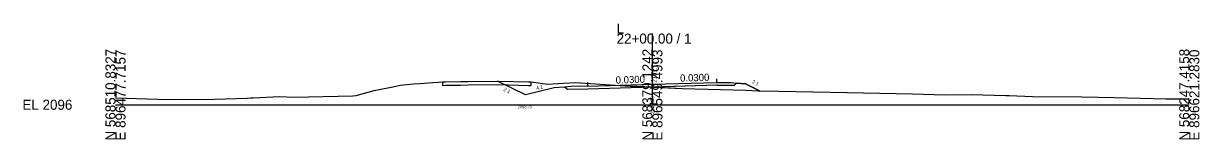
# Model space of a CAD drawing. Extents: x -26 to 1603, y -10 to 13527.
# Drawn here: x -25.7 to 302.8, y 9490.3 to 9522.7 of the extents above; entities that cross this region are included whole.
import ezdxf

# ---------------------------------------------------------------- set-up
doc = ezdxf.new("R2010")
doc.units = 0
for name, color, linetype in [('Default', 7, 'Continuous'), ('Exist XS Center Line Elevation Label', 7, 'Continuous'), ('Exist XS Ground Line', 7, 'Continuous'), ('Old_Level_61', 7, 'Continuous'), ('Old_Level_63', 7, 'Continuous'), ('Prop XS Ditch Slope Text', 7, 'Continuous'), ('Prop XS Ditch Standard Text', 7, 'Continuous'), ('Prop XS Earthwork Shape', 7, 'Continuous'), ('Prop XS EOT Tick Mark', 7, 'Continuous'), ('Prop XS Finish Grade', 7, 'Continuous'), ('Prop XS Finish Grade Earthwork', 7, 'Continuous'), ('Prop XS Finish Grade Paved Shoulder', 7, 'Continuous'), ('Prop XS Finish Grade Pavement', 7, 'Continuous'), ('Prop XS Side Slope Text', 7, 'Continuous'), ('Prop XS Subgrade Earthwork', 7, 'Continuous'), ('Prop XSC Text', 7, 'Continuous')]:
    doc.layers.add(name, color=color, linetype=linetype)

msp = doc.modelspace()

# ---------------------------------------------------------------- linework, layer by layer
at = {"layer": 'Exist XS Ground Line'}
for p, q in [((73.7, 9504.24), (77.47, 9505)), ((77.47, 9505), (79.57, 9505.46)), ((79.57, 9505.46), (83.26, 9505.8)), ((83.26, 9505.8), (85.12, 9505.92)), ((85.12, 9505.92), (88.7, 9506.17)), ((88.7, 9506.17), (90.23, 9506.28)), ((90.23, 9506.28), (91.4, 9506.41)), ((91.4, 9506.41), (92.17, 9506.44)), ((92.17, 9506.44), (96.35, 9506.49)), ((96.35, 9506.49), (98.55, 9506.52)), ((98.55, 9506.52), (107.03, 9506.62)), ((107.03, 9506.62), (115.41, 9506.39)), ((115.41, 9506.39), (116.12, 9506.37)), ((116.12, 9506.37), (116.74, 9506.27)), ((116.74, 9506.27), (120.68, 9505.73)), ((120.68, 9505.73), (123.55, 9505.9)), ((123.55, 9505.9), (128.49, 9506.25)), ((128.49, 9506.25), (142.4, 9505.31)), ((142.4, 9505.31), (143.8, 9505.21)), ((143.8, 9505.21), (145.77, 9505.15)), ((145.77, 9505.15), (150, 9504.96)), ((150, 9504.96), (158.32, 9504.57)), ((158.32, 9504.57), (165.45, 9504.39)), ((0, 9501.95), (11.83, 9501.6)), ((11.83, 9501.6), (18.94, 9501.44)), ((18.94, 9501.44), (21.67, 9501.53)), ((21.67, 9501.53), (24.64, 9501.5)), ((24.64, 9501.5), (36.8, 9501.87)), ((36.8, 9501.87), (37.74, 9501.92)), ((37.74, 9501.92), (38.45, 9501.94)), ((38.45, 9501.94), (45.83, 9502.34)), ((45.83, 9502.34), (49.83, 9502.16)), ((49.83, 9502.16), (66.28, 9502.5)), ((66.28, 9502.5), (67.26, 9502.6)), ((67.26, 9502.6), (72.3, 9503.95)), ((72.3, 9503.95), (73.7, 9504.24)), ((165.45, 9504.39), (176.1, 9504.04)), ((176.1, 9504.04), (179.59, 9503.91)), ((179.59, 9503.91), (185.22, 9503.8)), ((185.22, 9503.8), (204.39, 9503.4)), ((204.39, 9503.4), (208.98, 9503.31)), ((208.98, 9503.31), (222.71, 9503.04)), ((222.71, 9503.04), (231.83, 9502.76)), ((231.83, 9502.76), (239.03, 9502.83)), ((239.03, 9502.83), (248.71, 9502.55)), ((248.71, 9502.55), (249.64, 9502.55)), ((249.64, 9502.55), (256.21, 9502.34)), ((256.21, 9502.34), (269.98, 9502.21)), ((269.98, 9502.21), (279.08, 9502.07)), ((279.08, 9502.07), (293.48, 9501.63)), ((293.48, 9501.63), (293.85, 9501.63)), ((293.85, 9501.63), (300, 9501.67))]:
    msp.add_line(p, q, dxfattribs=at)
at = {"layer": 'Old_Level_61'}
for p, q in [((91.4, 9506.41), (91.4, 9505.41)), ((91.4, 9505.41), (92.17, 9505.44)), ((92.17, 9505.44), (92.59, 9505.44)), ((92.59, 9505.44), (96.35, 9505.49)), ((96.35, 9505.49), (98.55, 9505.52)), ((98.55, 9505.52), (107.03, 9505.62)), ((107.03, 9505.62), (115.41, 9505.39)), ((115.41, 9505.39), (116.12, 9505.37)), ((116.12, 9505.37), (116.12, 9506.37))]:
    msp.add_line(p, q, dxfattribs=at)
at = {"layer": 'Old_Level_63'}
for p, q in [((150, 9500), (150, 9519.87)), ((0, 9500), (150, 9500)), ((150, 9500), (300, 9500))]:
    msp.add_line(p, q, dxfattribs=at)
at = {"layer": 'Prop XS Earthwork Shape'}
for points in [[(106.74, 9506.62), (107.03, 9506.62), (115.41, 9506.39), (116.12, 9506.37), (116.74, 9506.27), (120.68, 9505.73), (123.55, 9505.9), (128.49, 9506.25), (142.4, 9505.31), (143.8, 9505.21), (145.77, 9505.15), (150, 9504.96), (150.47, 9504.94), (150, 9504.92), (132, 9504.38), (126.29, 9504.24), (125.46, 9504.93), (122.51, 9504.73), (114.51, 9502.73)], [(165.45, 9504.39), (176.1, 9504.04), (179.59, 9503.91), (179.91, 9503.9), (176, 9505.85), (173.5, 9506.05), (172.81, 9505.37), (168, 9505.46), (150.47, 9504.94), (158.32, 9504.57)]]:
    msp.add_lwpolyline(points, close=True, dxfattribs=at)
at = {"layer": 'Prop XS EOT Tick Mark'}
for p, q in [((132, 9505.17), (132, 9506.17)), ((168, 9506.25), (168, 9507.25))]:
    msp.add_line(p, q, dxfattribs=at)
at = {"layer": 'Prop XS Finish Grade'}
for p, q in [((127.26, 9505.05), (125.46, 9504.93)), ((172, 9506.17), (173.5, 9506.05))]:
    msp.add_line(p, q, dxfattribs=at)
at = {"layer": 'Prop XS Finish Grade Earthwork'}
for p, q in [((114.51, 9502.73), (106.74, 9506.62)), ((122.51, 9504.73), (114.51, 9502.73)), ((125.46, 9504.93), (122.51, 9504.73)), ((173.5, 9506.05), (176, 9505.85)), ((176, 9505.85), (179.91, 9503.9))]:
    msp.add_line(p, q, dxfattribs=at)
at = {"layer": 'Prop XS Finish Grade Paved Shoulder'}
for p, q in [((132, 9505.17), (127.26, 9505.05)), ((168, 9506.25), (172, 9506.17))]:
    msp.add_line(p, q, dxfattribs=at)
at = {"layer": 'Prop XS Finish Grade Pavement'}
for p, q in [((132, 9505.17), (150, 9505.71)), ((150, 9505.71), (168, 9506.25))]:
    msp.add_line(p, q, dxfattribs=at)
at = {"layer": 'Prop XS Subgrade Earthwork'}
for p, q in [((126.29, 9504.24), (125.46, 9504.93)), ((150, 9504.92), (132, 9504.38)), ((168, 9505.46), (150, 9504.92)), ((168, 9505.46), (172.81, 9505.37)), ((172.81, 9505.37), (173.5, 9506.05)), ((132, 9504.38), (126.29, 9504.24))]:
    msp.add_line(p, q, dxfattribs=at)

# ---------------------------------------------------------------- texts
at = {"layer": 'Default'}
for p in [(139.76, 9505.9), (157.76, 9506.44)]:
    msp.add_text('0.0300', height=2, rotation=1.7184, dxfattribs=at).set_placement(p)
at = {"layer": 'Exist XS Center Line Elevation Label'}
msp.add_text('2100.96', height=1, rotation=90, dxfattribs=at).set_placement((150.5, 9497.37))
at = {"layer": 'Old_Level_63'}
for s, p in [('L', (140, 9519.87)), ('22+00.00 / 1', (140, 9517.07)), ('EL 2096', (-26, 9498.6))]:
    msp.add_text(s, height=2.8, dxfattribs=at).set_placement(p)
for s, p in [('N 568510.8327', (0, 9490)), ('E 896477.7157', (2.8, 9490)), ('N 568379.1242', (150, 9490)), ('E 896549.4993', (152.8, 9490)), ('N 568247.4158', (300, 9490)), ('E 896621.2830', (302.8, 9490))]:
    msp.add_text(s, height=2.8, rotation=90, dxfattribs=at).set_placement(p)
at = {"layer": 'Prop XS Ditch Slope Text'}
msp.add_text('4:1', height=1, rotation=14.0351, dxfattribs=at).set_placement((117.67, 9504.1))
at = {"layer": 'Prop XS Ditch Standard Text'}
msp.add_text('2098.73', height=0.8, dxfattribs=at).set_placement((112.38, 9499.02))
at = {"layer": 'Prop XS Side Slope Text'}
for rotation, p in [(333.4369, (108.27, 9503.97)), (333.4349, (177.72, 9506.11))]:
    msp.add_text('2:1', height=1, rotation=rotation, dxfattribs=at).set_placement(p)
at = {"layer": 'Prop XSC Text'}
msp.add_text(' 2101.71', height=1.2, rotation=90, dxfattribs=at).set_placement((151.2, 9505.71))

doc.saveas('drawing.dxf')
